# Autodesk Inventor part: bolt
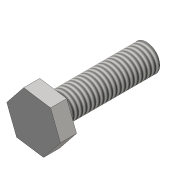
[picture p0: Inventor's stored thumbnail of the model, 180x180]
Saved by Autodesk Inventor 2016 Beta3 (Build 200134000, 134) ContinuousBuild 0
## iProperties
Created: 2016-03
Part Number: bolt
Material: Generic
Document SubType Name: Modeling
Designer: Gaurav
Density: 1 g/cm^3
Appearance: Default
Author: Gaurav
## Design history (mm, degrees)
sketch "Sketch1"
  geometry: L1 (-1.842, -4.71)-(-5, -0.76); L2 (-5, -0.76)-(-3.158, 3.95); L3 (-3.158, 3.95)-(1.842, 4.71); L4 (1.842, 4.71)-(5, 0.76); L5 (5, 0.76)-(3.158, -3.95); L6 (3.158, -3.95)-(-1.842, -4.71); 2 further points
  constraints: 12 end point, 1 coincident, 13 other
  dimensions: "d0" = 5 horizontal distance of L2.end L3.end
extrude "Extrusion1" new body sketch "Sketch1" distance "d1" = 3; taper "d2" = 0 deg
sketch "Sketch2"
  geometry: C1 r 2.5 at (0, 0); 1 further point
  constraints: 1 centre point, 1 coincident
  dimensions: "d3" = 5 diameter of C1
extrude "Extrusion2" join sketch "Sketch2" distance "d4" = 18; taper "d5" = 0 deg
thread "Thread1" dims "d6" = 10, "d7" = 0
body "Solid1"
